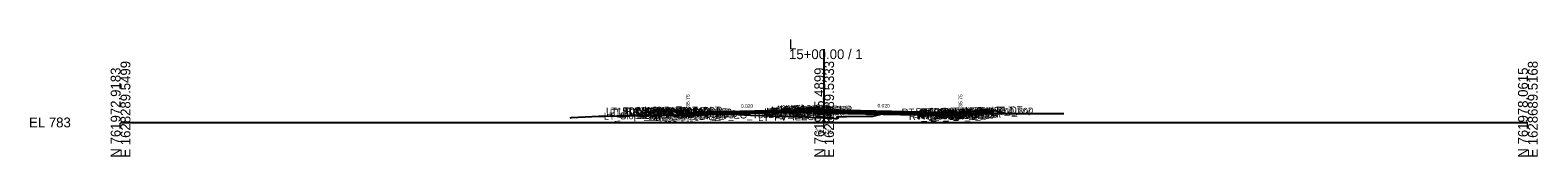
# Model space of a CAD drawing. Extents: x -26 to 4403, y -510 to 9556.
# Drawn here: x -25.7 to 402.8, y 4990.3 to 5023.6 of the extents above; entities that cross this region are included whole.
import ezdxf

# ---------------------------------------------------------------- set-up
doc = ezdxf.new("R2010")
doc.units = 0
for name, color, linetype in [('Default', 7, 'Continuous'), ('Exist CMT Pavement', 7, 'Continuous'), ('Exist Cross Section Cell', 7, 'Continuous'), ('Exist XS Center Line Elevation Label', 7, 'Continuous'), ('Exist XS Ground Line', 7, 'Continuous'), ('Exist XS Void Line', 7, 'Continuous'), ('Prop CMT Conc Surface', 7, 'Continuous'), ('Prop CMT Concrete Structures', 7, 'Continuous'), ('Prop CMT Pvmt Course 1', 7, 'Continuous'), ('Prop CMT Pvmt Course 1 CG', 7, 'Continuous'), ('Prop CMT Pvmt Course 1 Wedge', 7, 'Continuous'), ('Prop CMT Pvmt Course 2', 7, 'Continuous'), ('Prop CMT Pvmt Course 2 Wedge', 7, 'Continuous'), ('Prop CMT Pvmt Course 3', 7, 'Continuous'), ('Prop CMT Pvmt Course 3 Wedge', 7, 'Continuous'), ('Prop CMT Pvmt Surface', 7, 'Continuous'), ('Prop CMT Pvmt Wedge Surface 1', 7, 'Continuous'), ('Prop CMT Pvmt Wedge Surface 2', 7, 'Continuous'), ('Prop CMT Pvmt Wedge Surface 3', 7, 'Continuous'), ('Prop CMT Slope Grass', 7, 'Continuous'), ('Prop CMT Subgrade Earthwork', 7, 'Continuous'), ('Prop XS Hydro Elevations', 7, 'Continuous'), ('Prop XS SE Text', 7, 'Continuous'), ('Prop XS Side Slope Text', 7, 'Continuous'), ('Scratch_Level_0', 7, 'Continuous')]:
    doc.layers.add(name, color=color, linetype=linetype)

msp = doc.modelspace()

# ---------------------------------------------------------------- linework, layer by layer
at = {"layer": 'Exist CMT Pavement'}
msp.add_lwpolyline([(163.25, 5002.25), (172.13, 5002.41), (179.06, 5002.11), (194.47, 5001.56), (199.68, 5001.36), (200, 5001.35), (201.67, 5001.29)], dxfattribs=at)
at = {"layer": 'Exist Cross Section Cell'}
for p, q in [((200, 5000), (200, 5020.8)), ((0, 5000), (200, 5000)), ((200, 5000), (400, 5000))]:
    msp.add_line(p, q, dxfattribs=at)
at = {"layer": 'Exist XS Ground Line'}
msp.add_lwpolyline([(127.78, 5001.35), (128.14, 5001.43), (135.91, 5001.75), (136.31, 5001.76), (137.8, 5001.79), (141.09, 5001.86), (144.62, 5001.93), (158.56, 5002.17), (172.13, 5002.41), (179.06, 5002.11), (194.47, 5001.56), (199.68, 5001.36), (200, 5001.35), (201.67, 5001.29), (203.7, 5001.14), (203.7, 5001.64), (204.2, 5001.64), (206, 5001.68), (206.33, 5001.68), (212.03, 5001.79), (213.82, 5001.82), (215.76, 5002.3), (216.63, 5002.52)], dxfattribs=at)
at = {"layer": 'Exist XS Void Line'}
msp.add_line((216.63, 5002.52), (268.09, 5002.52), dxfattribs=at)
at = {"layer": 'Prop CMT Conc Surface'}
for points in [[(156.75, 5003.34), (151.75, 5003.44)], [(161.25, 5002.75), (161.25, 5003.25), (160.75, 5003.25)], [(163.25, 5002.87), (161.25, 5002.75)], [(236.75, 5002.87), (238.75, 5002.75)], [(238.75, 5002.75), (238.75, 5003.25), (239.25, 5003.25)], [(243.25, 5003.34), (248.25, 5003.44)]]:
    msp.add_lwpolyline(points, dxfattribs=at)
at = {"layer": 'Prop CMT Concrete Structures'}
for points in [[(151.75, 5003.1), (151.75, 5003.44)], [(151.75, 5003.44), (156.75, 5003.34)], [(156.75, 5003), (151.75, 5003.1)], [(156.75, 5003.34), (156.75, 5003)], [(163.25, 5002.87), (161.25, 5002.75), (161.25, 5003.25), (160.75, 5003.25)], [(160.75, 5003.25), (160.75, 5002.23), (163.25, 5002.28)], [(163.25, 5002.28), (163.25, 5002.87)], [(197.01, 5003.66), (197, 5003.83), (196.25, 5004.08), (195.01, 5004.1), (193.77, 5003.88), (193.02, 5003.63), (193.01, 5003.46)], [(193.01, 5003.46), (197.01, 5003.66)], [(236.75, 5002.87), (238.75, 5002.75), (238.75, 5003.25), (239.25, 5003.25)], [(239.25, 5003.25), (239.25, 5002.23), (236.75, 5002.28)], [(236.75, 5002.28), (236.75, 5002.87)], [(248.25, 5003.44), (243.25, 5003.34)], [(243.25, 5003.34), (243.25, 5003)], [(243.25, 5003), (248.25, 5003.1)], [(248.25, 5003.1), (248.25, 5003.44)]]:
    msp.add_lwpolyline(points, dxfattribs=at)
at = {"layer": 'Prop CMT Pvmt Course 1'}
for points in [[(193.01, 5003.46), (163.25, 5002.87)], [(163.25, 5002.74), (193.01, 5003.34)], [(163.25, 5002.87), (163.25, 5002.62), (163.25, 5002.62), (163.25, 5002.74)], [(193.01, 5003.46), (197.01, 5003.66)], [(193.01, 5003.21), (193.01, 5003.46)], [(193.01, 5003.21), (193.01, 5003.46)], [(197.01, 5003.41), (193.01, 5003.21)], [(193.01, 5003.34), (193.01, 5003.21), (193.01, 5003.21)], [(197.01, 5003.66), (197.01, 5003.41)], [(197.01, 5003.66), (236.75, 5002.87)], [(197.01, 5003.41), (197.01, 5003.66)], [(236.75, 5002.62), (197.01, 5003.41)], [(236.75, 5002.87), (236.75, 5002.62)]]:
    msp.add_lwpolyline(points, dxfattribs=at)
msp.add_lwpolyline([(197.01, 5003.41), (197.01, 5003.54), (197.01, 5003.54), (197.01, 5003.41)], close=True, dxfattribs=at)
at = {"layer": 'Prop CMT Pvmt Course 1 CG'}
for points in [[(163.25, 5002.28), (160.25, 5002.22), (159.91, 5001.88)], [(159.91, 5001.88), (163.25, 5001.95)], [(163.25, 5001.95), (163.25, 5002.28)], [(236.75, 5002.28), (239.75, 5002.22), (240.09, 5001.88)], [(236.75, 5001.95), (236.75, 5002.28)], [(240.09, 5001.88), (236.75, 5001.95)]]:
    msp.add_lwpolyline(points, dxfattribs=at)
at = {"layer": 'Prop CMT Pvmt Course 1 Wedge'}
for points in [[(163.25, 5002.74), (172.13, 5002.92), (179.06, 5003.06), (193.01, 5003.34)], [(193.01, 5003.21), (179.06, 5002.93), (172.13, 5002.79), (163.25, 5002.62)], [(163.25, 5002.62), (163.25, 5002.74)], [(193.01, 5003.34), (193.01, 5003.21)]]:
    msp.add_lwpolyline(points, dxfattribs=at)
at = {"layer": 'Prop CMT Pvmt Course 2'}
for points in [[(163.25, 5002.28), (163.25, 5002.28), (163.25, 5002.62), (163.25, 5002.62)], [(163.25, 5002.62), (163.25, 5002.28)], [(193.01, 5003.21), (197.01, 5003.41)], [(193.01, 5002.88), (193.01, 5003.21)], [(197.01, 5003.08), (193.01, 5002.88)], [(197.01, 5003.41), (197.01, 5003.08)], [(197.01, 5003.08), (197.01, 5003.41)], [(197.01, 5003.41), (236.75, 5002.62)], [(236.75, 5002.28), (197.01, 5003.08)], [(236.75, 5002.62), (236.75, 5002.28)]]:
    msp.add_lwpolyline(points, dxfattribs=at)
at = {"layer": 'Prop CMT Pvmt Course 2 Wedge'}
for points in [[(163.25, 5002.62), (172.13, 5002.79), (179.06, 5002.93), (193.01, 5003.21)], [(193.01, 5002.88), (179.06, 5002.6), (172.13, 5002.46), (163.25, 5002.28)], [(163.25, 5002.28), (163.25, 5002.62)], [(193.01, 5003.21), (193.01, 5002.88)]]:
    msp.add_lwpolyline(points, dxfattribs=at)
at = {"layer": 'Prop CMT Pvmt Course 3'}
for points in [[(163.25, 5002.28), (163.25, 5002.28), (163.25, 5001.95), (163.25, 5001.95)], [(163.25, 5001.95), (163.25, 5002.28)], [(193.01, 5002.88), (197.01, 5003.08)], [(197.01, 5003.08), (236.75, 5002.28)], [(236.75, 5001.95), (201.67, 5002.65)], [(236.75, 5002.28), (236.75, 5001.95)]]:
    msp.add_lwpolyline(points, dxfattribs=at)
at = {"layer": 'Prop CMT Pvmt Course 3 Wedge'}
for points in [[(163.25, 5002.28), (172.13, 5002.46), (179.06, 5002.6), (193.01, 5002.88)], [(163.25, 5002.25), (163.25, 5002.28)]]:
    msp.add_lwpolyline(points, dxfattribs=at)
at = {"layer": 'Prop CMT Pvmt Surface'}
for points in [[(193.01, 5003.46), (163.25, 5002.87)], [(193.01, 5003.46), (197.01, 5003.66)], [(197.01, 5003.66), (236.75, 5002.87)]]:
    msp.add_lwpolyline(points, dxfattribs=at)
at = {"layer": 'Prop CMT Pvmt Wedge Surface 1'}
for points in [[(193.01, 5003.34), (163.25, 5002.74)], [(163.25, 5002.62), (163.25, 5002.87)], [(163.25, 5002.74), (163.25, 5002.62), (163.25, 5002.62)], [(193.01, 5003.46), (193.01, 5003.21), (193.01, 5003.21), (193.01, 5003.34)]]:
    msp.add_lwpolyline(points, dxfattribs=at)
at = {"layer": 'Prop CMT Pvmt Wedge Surface 2'}
for points in [[(193.01, 5003.21), (163.25, 5002.62)], [(163.25, 5002.62), (163.25, 5002.87)], [(193.01, 5003.46), (193.01, 5003.21)]]:
    msp.add_lwpolyline(points, dxfattribs=at)
at = {"layer": 'Prop CMT Pvmt Wedge Surface 3'}
for points in [[(193.01, 5002.88), (163.25, 5002.28)], [(163.25, 5002.28), (163.25, 5002.87)], [(193.01, 5003.46), (193.01, 5002.88)]]:
    msp.add_lwpolyline(points, dxfattribs=at)
at = {"layer": 'Prop CMT Slope Grass'}
msp.add_line((248.75, 5003.44), (251.51, 5002.52), dxfattribs=at)
for points in [[(160.75, 5003.25), (151.25, 5003.44), (146.84, 5001.97)], [(239.25, 5003.25), (248.25, 5003.43)], [(248.25, 5003.43), (248.75, 5003.44)]]:
    msp.add_lwpolyline(points, dxfattribs=at)
at = {"layer": 'Prop CMT Subgrade Earthwork'}
msp.add_line((201.67, 5002.65), (201.67, 5001.29), dxfattribs=at)
for points in [[(163.25, 5001.95), (159.91, 5001.88), (158.5, 5003.29)], [(163.25, 5001.95), (163.25, 5002.25)], [(163.25, 5001.95), (163.25, 5001.95)], [(201.67, 5002.65), (236.75, 5001.95)], [(236.75, 5001.95), (240.09, 5001.88), (241.5, 5003.29)]]:
    msp.add_lwpolyline(points, dxfattribs=at)

# ---------------------------------------------------------------- texts
at = {"layer": 'Default'}
msp.add_text('-', height=0.0001, dxfattribs=at).set_placement((0, 5000))
at = {"layer": 'Exist Cross Section Cell'}
for s, p in [('L', (190, 5020.8)), ('15+00.00 / 1', (190, 5018)), ('EL 783', (-26, 4998.6))]:
    msp.add_text(s, height=2.8, dxfattribs=at).set_placement(p)
for s, p in [('N 761972.9183', (0, 4990)), ('E 1628289.5499', (2.8, 4990)), ('N 761975.4899', (200, 4990)), ('E 1628489.5333', (202.8, 4990)), ('N 761978.0615', (400, 4990)), ('E 1628689.5168', (402.8, 4990))]:
    msp.add_text(s, height=2.8, rotation=90, dxfattribs=at).set_placement(p)
at = {"layer": 'Exist XS Center Line Elevation Label'}
msp.add_text('784.35', height=1.2, dxfattribs=at).set_placement((197.42, 4996.75))
at = {"layer": 'Prop XS Hydro Elevations'}
for p in [(161.75, 5003.75), (239.25, 5003.75)]:
    msp.add_text('785.75', height=1, rotation=90, dxfattribs=at).set_placement(p)
at = {"layer": 'Prop XS SE Text'}
for rotation, p in [(358.8539, (215.15, 5004.3)), (1.1453, (176.36, 5004.13))]:
    msp.add_text('0.020', height=1, rotation=rotation, dxfattribs=at).set_placement(p)
at = {"layer": 'Prop XS Side Slope Text'}
for rotation, p in [(18.4296, (148.05, 5003.16)), (341.5651, (249.49, 5003.8))]:
    msp.add_text('3:1', height=1, rotation=rotation, dxfattribs=at).set_placement(p)
at = {"layer": 'Scratch_Level_0'}
for s, p in [('LT_Slope_Fill', (137.38, 5000.78)), ('LT_SDWK_Out_Top', (138.01, 5002.16)), ('LT_SDWK_Out_Bot', (138.04, 5001.83)), ('LT_Sub_Trench_Out_DLT', (139.09, 5001.9)), ('LT_CSLP_Pnt', (141.44, 5002.24)), ('LT_SDWK_In_Top', (144.63, 5002.09)), ('LT_SDWK_In_Bot', (144.66, 5001.76)), ('LT_CG1_Shelf_Out', (146.82, 5000.95)), ('LT_PV_Sub_Tie_Out', (148.23, 5000.95)), ('LT_CG_Top_Face', (148.53, 5001.99)), ('15+00.00', (148.99, 5002.24)), ('LT_CG_Top_BOC', (149.06, 5002.01)), ('LT_CG_Bot_BOC', (149.09, 5001)), ('LT_CG_Top_Gut', (149.51, 5001.51)), ('LT_Sub_OEOP', (150.04, 5000.69)), ('LT_Sub_OEOT_CG', (150.64, 5000.7)), ('LT_PV_OEEOP_EG', (150.82, 5001)), ('15+00.00', (151.22, 5002.19)), ('LT_Sub_OEEOP', (152.48, 5000.73)), ('LT_PV2_OEEOP', (152.58, 5001.4)), ('LT_PV3_OEEOP', (152.58, 5001.07)), ('LT_PV1_OEEOP', (153.15, 5001.54)), ('LT_CG_Bot_IE', (153.18, 5001.08)), ('LT_Sub_OEOT', (153.35, 5000.75)), ('LT_PV2_OEOT', (153.44, 5001.42)), ('LT_PV3_OEOT', (153.44, 5001.09)), ('LT_PV1_OEOT', (154.01, 5001.68)), ('15+00.00', (154.69, 5002.12)), ('15+00.00', (155.98, 5001.68)), ('LT_PV_EG_TestPt', (164.56, 5000.88)), ('LT_PV_IEEOP_EG', (181.22, 5000.37)), ('LT_PV2_IEEOP', (182.98, 5002.01)), ('LT_PV3_IEEOP', (182.98, 5001.68)), ('LT_PV1_IEEOP', (183.55, 5002.15)), ('LT_PV2_PGL1', (183.91, 5002.03)), ('LT_PV3_PGL1', (183.91, 5001.7)), ('LT_PV2_PGL', (184.24, 5002.04)), ('LT_PV3_PGL', (184.24, 5001.7)), ('LT_PV4_PGL', (184.24, 5001.37)), ('LT_PV1_PGL', (184.81, 5002.3)), ('MI_Face In', (184.93, 5002.47)), ('RT_Sub_OEEOP', (186.2, 5001.53)), ('RT_PV2_OEEOP', (186.29, 5002.2)), ('RT_PV3_OEEOP', (186.29, 5001.86)), ('MI_Top In', (186.64, 5002.74)), ('RT_PV1_OEEOP', (186.86, 5002.33)), ('RT_PV2_IEEOP', (186.94, 5002.21)), ('15+00.00', (187.1, 5002.61)), ('MI_Face Out', (187.29, 5002.63)), ('MI_Top Out', (187.5, 5002.9)), ('RT_PV1_IEEOP', (187.5, 5002.35)), ('RT_PV2_PGL1', (187.87, 5002.23)), ('RT_PV3_PGL1', (187.87, 5001.89)), ('MI_Crown', (188.1, 5002.96)), ('RT_PV2_PGL', (188.2, 5002.23)), ('RT_PV4_PGL', (188.2, 5001.57)), ('MI_Bot Out', (188.29, 5002.49)), ('RT_PV1_PGL', (188.76, 5002.5)), ('15+00.00', (190.37, 5002.83)), ('RT_Sub_Trench_Out_DLT', (222.04, 5001.9)), ('RT_Sub_OEOT_CG', (224.1, 5000.7)), ('RT_CG_Top_Face', (225.99, 5001.99)), ('RT_CG1_Shelf_Out', (226.28, 5000.95)), ('RT_CG_Bot_IE', (226.64, 5001.08)), ('RT_Sub_OEOT', (226.8, 5000.75)), ('RT_PV2_OEOT', (226.9, 5001.42)), ('RT_PV3_OEOT', (226.9, 5001.09)), ('RT_CG_Top_Gut', (226.96, 5001.51)), ('RT_PV1_OEOT', (227.46, 5001.68)), ('RT_CG_Top_BOC', (227.51, 5002.01)), ('RT_CG_Bot_BOC', (227.54, 5001)), ('RT_Sub_OEOP', (230.17, 5000.68)), ('RT_SDWK_In_Top', (231.08, 5002.09)), ('RT_SDWK_In_Bot', (231.12, 5001.76)), ('15+00.00', (232.65, 5002.12)), ('15+00.00', (234.01, 5002.14)), ('RT_SDWK_Out_Top', (234.46, 5002.16)), ('RT_SDWK_Out_Bot', (234.49, 5001.83)), ('RT_Shld_O', (240.81, 5002.28))]:
    msp.add_text(s, height=2, rotation=1.1458, dxfattribs=at).set_placement(p)

doc.saveas('drawing.dxf')
